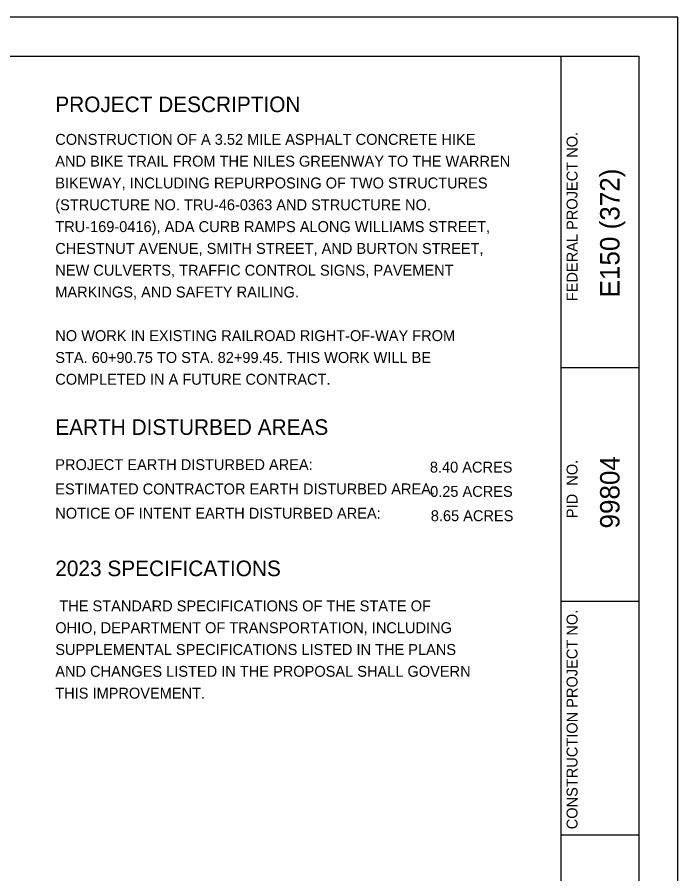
# Model space of a CAD drawing. Extents: x -37878.7 to -37844.7, y -19791.4 to -19769.4.
# Drawn here: x -37853.14 to -37844.65, y -19780.39 to -19769.39 of the extents above; entities that cross this region are included whole.
import ezdxf

# ---------------------------------------------------------------- set-up
doc = ezdxf.new("R2010")
doc.units = 0
for name, color, linetype in [('SH_Border', 7, 'Continuous'), ('SH_Cut_Line', 7, 'Continuous'), ('SH_Data', 7, 'Continuous')]:
    doc.layers.add(name, color=color, linetype=linetype)

msp = doc.modelspace()

# ---------------------------------------------------------------- linework, layer by layer
at = {"layer": 'SH_Border'}
for p, q in [((-37846.15, -19790.885), (-37846.15, -19769.885)), ((-37846.15, -19773.885), (-37845.15, -19773.885)), ((-37846.15, -19776.885), (-37845.15, -19776.885)), ((-37846.15, -19779.885), (-37845.15, -19779.885))]:
    msp.add_line(p, q, dxfattribs=at)
msp.add_lwpolyline([(-37876.65, -19769.885), (-37845.15, -19769.885), (-37845.15, -19790.885), (-37876.65, -19790.885)], close=True, dxfattribs=at)
at = {"layer": 'SH_Cut_Line'}
msp.add_lwpolyline([(-37878.65, -19791.385), (-37844.65, -19791.385), (-37844.65, -19769.385), (-37878.65, -19769.385)], close=True, dxfattribs=at)

# ---------------------------------------------------------------- texts
at = {"layer": 'SH_Data'}
for s, height, p in [('PROJECT DESCRIPTION', 0.2, (-37852.65, -19770.605)), ('CONSTRUCTION OF A 3.52 MILE ASPHALT CONCRETE HIKE ', 0.14, (-37852.65, -19771.025)), ('AND BIKE TRAIL FROM THE NILES GREENWAY TO THE WARREN', 0.14, (-37852.65, -19771.305)), ('BIKEWAY, INCLUDING REPURPOSING OF TWO STRUCTURES', 0.14, (-37852.65, -19771.585)), ('(STRUCTURE NO. TRU-46-0363 AND STRUCTURE NO. ', 0.14, (-37852.65, -19771.865)), ('TRU-169-0416), ADA CURB RAMPS ALONG WILLIAMS STREET, ', 0.14, (-37852.65, -19772.145)), ('CHESTNUT AVENUE, SMITH STREET, AND BURTON STREET, ', 0.14, (-37852.65, -19772.425)), ('NEW CULVERTS, TRAFFIC CONTROL SIGNS, PAVEMENT ', 0.14, (-37852.65, -19772.705)), ('MARKINGS, AND SAFETY RAILING.', 0.14, (-37852.65, -19772.985)), ('NO WORK IN EXISTING RAILROAD RIGHT-OF-WAY FROM ', 0.14, (-37852.65, -19773.545)), ('STA. 60+90.75 TO STA. 82+99.45. THIS WORK WILL BE ', 0.14, (-37852.65, -19773.825)), ('COMPLETED IN A FUTURE CONTRACT.', 0.14, (-37852.65, -19774.105)), ('EARTH DISTURBED AREAS', 0.2, (-37852.65, -19774.749)), ('PROJECT EARTH DISTURBED AREA:', 0.14, (-37852.65, -19775.201)), ('8.40 ACRES', 0.14, (-37847.837, -19775.233)), ('ESTIMATED CONTRACTOR EARTH DISTURBED AREA:', 0.14, (-37852.65, -19775.513)), ('0.25 ACRES', 0.14, (-37847.834, -19775.545)), ('NOTICE OF INTENT EARTH DISTURBED AREA:', 0.14, (-37852.65, -19775.825)), ('8.65 ACRES', 0.14, (-37847.825, -19775.857)), ('2023 SPECIFICATIONS', 0.2, (-37852.65, -19776.563)), (' THE STANDARD SPECIFICATIONS OF THE STATE OF', 0.14, (-37852.65, -19777.015)), ('OHIO, DEPARTMENT OF TRANSPORTATION, INCLUDING', 0.14, (-37852.65, -19777.295)), ('SUPPLEMENTAL SPECIFICATIONS LISTED IN THE PLANS', 0.14, (-37852.65, -19777.575)), ('AND CHANGES LISTED IN THE PROPOSAL SHALL GOVERN ', 0.14, (-37852.65, -19777.855)), ('THIS IMPROVEMENT.', 0.14, (-37852.65, -19778.135))]:
    msp.add_text(s, height=height, dxfattribs=at).set_placement(p)
for s, height, p in [('FEDERAL PROJECT NO.', 0.14, (-37845.94, -19773.033)), ('E150 (372)', 0.25, (-37845.4, -19772.984)), ('PID  NO.', 0.14, (-37845.94, -19775.818)), ('99804', 0.25, (-37845.4, -19775.951)), ('CONSTRUCTION PROJECT NO.', 0.14, (-37845.94, -19779.813))]:
    msp.add_text(s, height=height, rotation=90, dxfattribs=at).set_placement(p)

doc.saveas('drawing.dxf')
